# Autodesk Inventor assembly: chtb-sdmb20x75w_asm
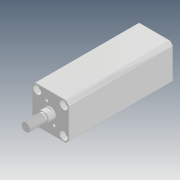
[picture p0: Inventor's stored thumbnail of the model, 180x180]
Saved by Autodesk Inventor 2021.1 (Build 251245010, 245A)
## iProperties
Company: Microsoft
Created: 2018-05
Part Number: chtb-sdmb20x75w_asm
Description: STEP AP214
Document SubType Name: Assembly
Designer: user
Title: chtb-sdmb20x75w_asm.STEP
Author: Windows
Revision Number: ÈÎºÎ
Sending System: SolidWorks 2015
Preprocessor: SwSTEP 2.0
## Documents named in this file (4)
- D:\Vault_2016\Projekty\Clamptek\Hydraulic\CHTB\CHTB-20\Inventor\CHTB-SDMB20x75W\chtb-sdmb20x75w_asm.iam
- D:\Vault_2016\Projekty\Clamptek\Hydraulic\CHTB\CHTB-20\Inventor\CHTB-SDMB20x75W\CHTB-SDMB20X75NBT.ipt
- D:\Vault_2016\Projekty\Clamptek\Hydraulic\CHTB\CHTB-20\Inventor\CHTB-SDMB20x75W\CHTB-SDMB20X75WHSG.ipt
- D:\Vault_2016\Projekty\Clamptek\Hydraulic\CHTB\CHTB-20\Inventor\CHTB-SDMB20x75W\QG_3.ipt
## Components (3 placed, 3 different names)
1. CHTB-SDMB20X75NBT_1
2. CHTB-SDMB20X75WHSG_2
3. QG_3_3
